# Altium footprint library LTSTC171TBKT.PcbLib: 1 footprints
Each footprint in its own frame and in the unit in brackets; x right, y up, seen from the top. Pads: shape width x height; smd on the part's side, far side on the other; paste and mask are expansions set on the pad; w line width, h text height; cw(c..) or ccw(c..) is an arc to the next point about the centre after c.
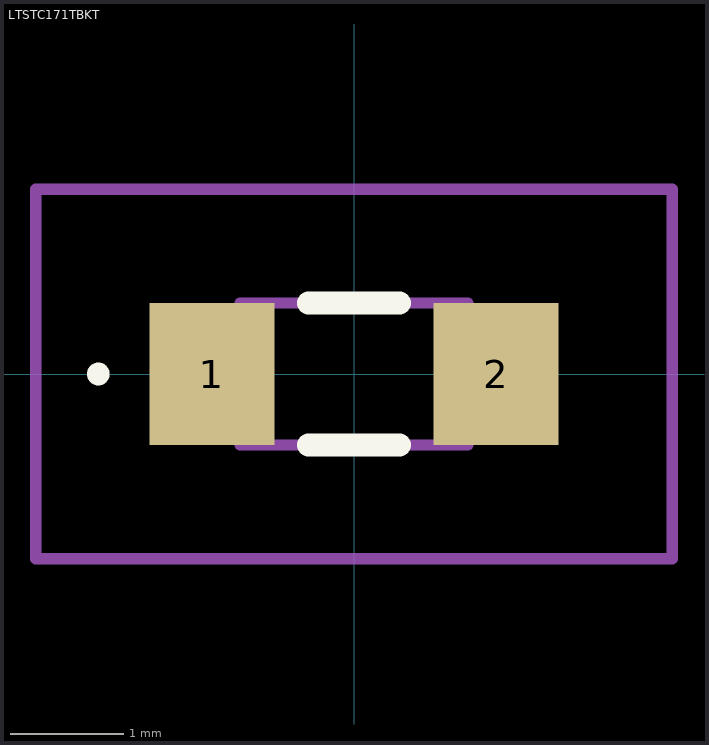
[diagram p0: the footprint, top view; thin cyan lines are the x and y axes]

## LTSTC171TBKT [mm]
pads (2):
  rect 1.1x1.25 smd: 1(-1.25,0) 2(1.25,0)
Top Overlay:
  lines w0.1: -2.3,0 cw(c-2.25,0) -2.2,0 ; -2.3,0 -2.3,0 ; -2.3,0 ccw(c-2.25,0) -2.2,0 ; -2.2,0 -2.2,0
  lines w0.2: -0.4,0.625 0.4,0.625 ; 0.4,-0.625 -0.4,-0.625 ; -0.4,-0.625 -0.4,-0.625
Mechanical 15:
  lines w0.1: -1,-0.625 1,-0.625 1,0.625 -1,0.625 -1,-0.625
Mechanical 20:
  lines w0.1: -2.8,-1.625 2.8,-1.625 2.8,1.625 -2.8,1.625 -2.8,-1.625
